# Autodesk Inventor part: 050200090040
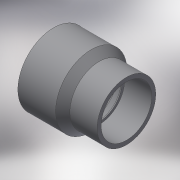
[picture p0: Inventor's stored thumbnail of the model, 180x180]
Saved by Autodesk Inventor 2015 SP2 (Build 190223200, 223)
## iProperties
Created: 2017-10
Part Number: 050200090040
Material: Generic
Description: PLASSON REDUCING SOCKET M.F.90(75)40 CEMENTED
Document SubType Name: Modeling
Designer: KIM
Density: 1 g/cm^3
Appearance: Default
Author: KIM
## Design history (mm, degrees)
derived "050200.ipt"
feature "Solid1::050200.ipt"
tag "TaggingFeature1"
body "Solid1"
other parameters: "d0" = 99, "d1" = 51, "d2" = 26, "d3" = 44, "d5" = 49, "d6" = 75, "d8" = 36, "d9" = 7.50119, "d12" = 0.75, "d_" = 75, "L_" = 51, "l_" = 44, "l_1" = 26, "E_" = 49, "H_" = 99, "d11" = 7.50119
